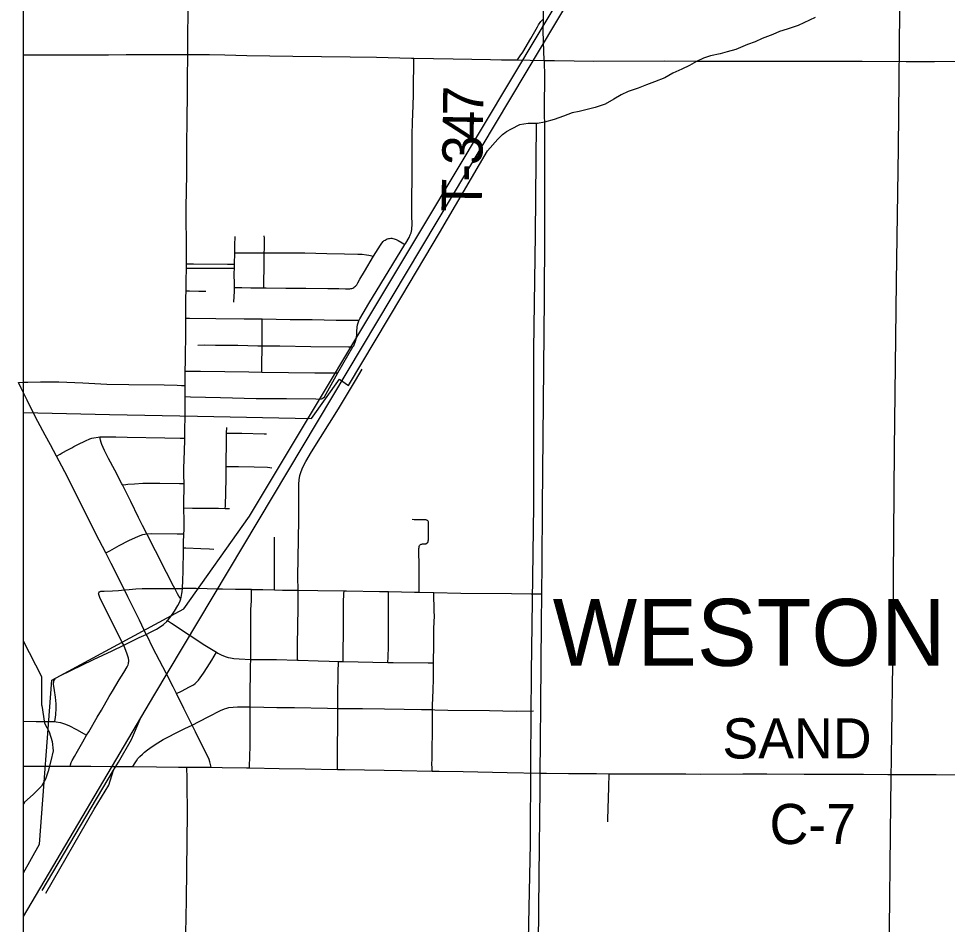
# Model space of a CAD drawing. Extents: x 0 to 680, y 0 to 834.
# Drawn here: x 44.4 to 94.9, y 268.9 to 318.1 of the extents above; entities that cross this region are included whole.
import ezdxf

# ---------------------------------------------------------------- set-up
doc = ezdxf.new("R2010")
doc.units = 0
for name, color, linetype in [('GM_X_City_Street', 7, 'Continuous'), ('GM_X_Corporation_Text', 7, 'Continuous'), ('GM_X_County_Road', 7, 'Continuous'), ('GM_X_County_Road_Text', 7, 'Continuous'), ('GM_X_Interstate_Route', 7, 'Continuous'), ('GM_X_Minor_River', 7, 'Continuous'), ('GM_X_Rail_Line', 7, 'Continuous'), ('GM_X_State_Route', 7, 'Continuous'), ('GM_X_Township_Road', 7, 'Continuous'), ('GM_X_Township_Road_Text', 7, 'Continuous')]:
    doc.layers.add(name, color=color, linetype=linetype)

msp = doc.modelspace()

# ---------------------------------------------------------------- linework, layer by layer
at = {"layer": 'GM_X_City_Street'}
for p, q in [((56.152, 304.76), (56.17, 305.388)), ((61.777, 298.858), (62.588, 300.27))]:
    msp.add_line(p, q, dxfattribs=at)
for points in [[(56.17, 305.388), (56.172, 305.444), (56.17, 305.803), (56.188, 306.278)], [(57.775, 305.391), (57.777, 305.6), (57.777, 306.184), (57.774, 306.301)], [(62.793, 300.988), (62.797, 301.108), (62.81, 301.349), (62.831, 301.466), (62.866, 301.581), (62.911, 301.692), (62.927, 301.724), (62.964, 301.8), (63.143, 302.113), (63.458, 302.626), (65.415, 305.836), (65.463, 305.915), (65.647, 306.223), (65.705, 306.361)], [(63.71, 305.198), (63.829, 305.398), (64.08, 305.807), (64.15, 305.908), (64.233, 306.001), (64.282, 306.046), (64.332, 306.08), (64.398, 306.117), (64.445, 306.138), (64.511, 306.158), (64.569, 306.169), (64.641, 306.175), (64.696, 306.173), (64.754, 306.164), (64.82, 306.15), (64.938, 306.108), (65.049, 306.054), (65.256, 305.93), (65.415, 305.836)], [(56.17, 305.388), (56.63, 305.388), (57.775, 305.391)], [(57.741, 303.485), (57.749, 303.843), (57.764, 304.545), (57.775, 305.391)], [(57.741, 303.485), (57.874, 303.483), (58.951, 303.466), (60.029, 303.464), (61.227, 303.442), (61.826, 303.439), (62.185, 303.421), (62.302, 303.421), (62.417, 303.43), (62.475, 303.442), (62.529, 303.455), (62.576, 303.471), (62.632, 303.499), (62.677, 303.529), (62.72, 303.564), (62.755, 303.6), (62.792, 303.649), (62.851, 303.748), (62.963, 303.962), (63.216, 304.369), (63.71, 305.198)], [(57.775, 305.391), (57.946, 305.392), (59.262, 305.384), (59.98, 305.377), (61.176, 305.347), (62.133, 305.334), (62.852, 305.319), (63.092, 305.305), (63.332, 305.273), (63.451, 305.249), (63.71, 305.198)], [(53.554, 304.793), (53.932, 304.789), (55.771, 304.765), (56.152, 304.76)], [(56.149, 304.543), (56.151, 304.728), (56.152, 304.76)], [(53.55, 304.555), (53.838, 304.548), (55.359, 304.545), (55.672, 304.544), (56.149, 304.543)], [(56.148, 303.5), (56.149, 303.655), (56.146, 304.252), (56.149, 304.543)], [(53.536, 303.323), (53.715, 303.319), (54.221, 303.309), (54.598, 303.31)], [(56.126, 302.698), (56.147, 303.296), (56.148, 303.5)], [(56.148, 303.5), (56.558, 303.494), (57.035, 303.489), (57.741, 303.485)], [(53.522, 301.839), (53.715, 301.836), (55.142, 301.821), (56.688, 301.801), (57.52, 301.792), (57.663, 301.789)], [(57.65, 300.335), (57.652, 300.754), (57.662, 301.458), (57.662, 301.575), (57.663, 301.789)], [(57.663, 301.789), (59.185, 301.769), (60.374, 301.754), (61.683, 301.73), (62.753, 301.725), (62.927, 301.724)], [(62.588, 300.27), (62.628, 300.339), (62.728, 300.592), (62.776, 300.771), (62.793, 300.988)], [(54.172, 300.375), (54.532, 300.38), (55.133, 300.371), (56.335, 300.359), (57.416, 300.339), (57.65, 300.335)], [(57.641, 298.904), (57.643, 299.228), (57.65, 300.335)], [(57.65, 300.335), (58.618, 300.323), (60.3, 300.299), (62.343, 300.273), (62.588, 300.27)], [(53.473, 297.571), (53.769, 297.564), (55.387, 297.523), (57.331, 297.474), (58.975, 297.463), (60.572, 297.443), (60.768, 297.433), (60.872, 297.447), (60.923, 297.466), (60.979, 297.505), (61.035, 297.567), (61.777, 298.858)], [(53.478, 298.954), (53.709, 298.957), (53.828, 298.959), (54.307, 298.953), (55.622, 298.937), (56.938, 298.913), (57.641, 298.904)], [(57.641, 298.904), (59.091, 298.884), (60.527, 298.864), (61.484, 298.86), (61.777, 298.858)], [(59.578, 283.256), (59.577, 283.474), (59.576, 284.073), (59.605, 286.107), (59.608, 286.826), (59.605, 287.051), (59.599, 287.783), (59.625, 289.818), (59.644, 290.893), (59.647, 292.447), (59.649, 292.806), (59.672, 293.045), (59.712, 293.281), (59.74, 293.397), (59.776, 293.511), (59.868, 293.732), (60.035, 294.05), (60.343, 294.564), (61.797, 296.904), (62.722, 298.444), (63.088, 299.063)], [(44.429, 298.336), (44.696, 298.351), (44.934, 298.365), (45.618, 298.383), (46.623, 298.371), (47.925, 298.32), (49.228, 298.251), (50.42, 298.222), (52.33, 298.206), (53.046, 298.194), (53.284, 298.183), (53.472, 298.175)], [(55.656, 291.495), (55.66, 291.637), (55.699, 293.115), (55.707, 293.772), (55.725, 295.287), (55.73, 295.589), (55.736, 295.89)], [(46.493, 294.343), (46.685, 294.452), (46.789, 294.511), (47.106, 294.684), (47.213, 294.733), (47.32, 294.789), (47.425, 294.853), (47.639, 294.965), (48.071, 295.177), (48.292, 295.271), (48.406, 295.309), (48.521, 295.338), (48.758, 295.373), (48.835, 295.379), (48.998, 295.391), (49.72, 295.39), (50.322, 295.371), (52.367, 295.338), (53.209, 295.322), (53.456, 295.317)], [(53.243, 286.578), (53.14, 286.731), (53.06, 286.85), (52.91, 287.151), (52.849, 287.276), (52.465, 288.018), (51.867, 289.193), (51.43, 290.044), (51.403, 290.118), (51.155, 290.574), (50.941, 291.003), (50.522, 291.868), (50.077, 292.771), (50.045, 292.837), (49.652, 293.579), (49.316, 294.216), (49.099, 294.644), (48.95, 294.971), (48.906, 295.083), (48.878, 295.198), (48.835, 295.379)], [(55.73, 295.589), (55.953, 295.588), (56.559, 295.583), (57.772, 295.55), (57.893, 295.55)], [(55.707, 293.772), (55.89, 293.772), (56.374, 293.771), (57.222, 293.758), (57.948, 293.731), (58.068, 293.721), (58.187, 293.697)], [(50.077, 292.771), (50.249, 292.795), (50.366, 292.811), (50.717, 292.84), (51.182, 292.862), (51.642, 292.873), (52.109, 292.871), (53.169, 292.854), (53.416, 292.85)], [(53.405, 291.524), (53.883, 291.518), (54, 291.514), (54.234, 291.507), (54.586, 291.502), (55.289, 291.506), (55.656, 291.495), (55.878, 291.489)], [(66.192, 286.949), (66.19, 287.19), (66.179, 288.255), (66.176, 289.319), (66.18, 289.373), (66.191, 289.436), (66.211, 289.478), (66.229, 289.507), (66.255, 289.533), (66.287, 289.55), (66.323, 289.562), (66.364, 289.57), (66.485, 289.568), (66.517, 289.571), (66.542, 289.577), (66.572, 289.586), (66.599, 289.599), (66.624, 289.619), (66.652, 289.651), (66.671, 289.693), (66.68, 289.737), (66.688, 289.792), (66.698, 290.503), (66.701, 290.622), (66.699, 290.692), (66.692, 290.74), (66.685, 290.769), (66.671, 290.799), (66.657, 290.821), (66.635, 290.842), (66.61, 290.858), (66.575, 290.867), (66.547, 290.872), (66.512, 290.875), (66.276, 290.88), (65.921, 290.881), (65.803, 290.888)], [(49.166, 289.076), (49.379, 289.196), (49.892, 289.484), (50.416, 289.751), (50.951, 289.995), (51.172, 290.078), (51.286, 290.104), (51.403, 290.118), (51.638, 290.127), (53.05, 290.113), (53.168, 290.114), (53.41, 290.115)], [(58.323, 287.072), (58.323, 287.175), (58.336, 289.927)], [(53.395, 289.355), (53.513, 289.351), (54.332, 289.322), (54.799, 289.302), (55.032, 289.285)], [(48.825, 286.968), (48.857, 286.983), (48.889, 286.994), (48.914, 287.001), (48.948, 287.004), (48.992, 287.006), (49.071, 287.006), (49.533, 287.012), (49.86, 287.036), (50.18, 287.068), (50.444, 287.1), (50.797, 287.126), (51.149, 287.141), (51.5, 287.15), (51.961, 287.154), (52.307, 287.153), (52.91, 287.151), (53.013, 287.152), (53.338, 287.153)], [(52.524, 285.406), (52.556, 285.439), (52.702, 285.623), (52.895, 285.919), (53.08, 286.22), (53.188, 286.428), (53.231, 286.537), (53.243, 286.578), (53.264, 286.649), (53.304, 286.881), (53.315, 286.961), (53.338, 287.153)], [(57.087, 287.086), (57.693, 287.084), (58.323, 287.072), (58.768, 287.064), (59.605, 287.051), (60.68, 287.035), (62.103, 287.02), (62.233, 287.019), (64.024, 286.985), (64.516, 286.977), (65.934, 286.955), (66.192, 286.949), (66.982, 286.932), (68.443, 286.9), (71.192, 286.866), (72.268, 286.857), (72.627, 286.857), (72.847, 286.858)], [(50.137, 284.063), (50.045, 284.247), (49.369, 285.607), (49.103, 286.132), (48.848, 286.661), (48.789, 286.819), (48.782, 286.846), (48.776, 286.871), (48.784, 286.916), (48.825, 286.968)], [(62.054, 283.177), (62.056, 283.386), (62.06, 283.725), (62.073, 284.757), (62.074, 285.587), (62.075, 286.162), (62.077, 286.506), (62.093, 286.741), (62.097, 286.86), (62.103, 287.02)], [(64.49, 283.126), (64.498, 283.416), (64.514, 283.986), (64.52, 284.832), (64.522, 285.196), (64.525, 285.661), (64.516, 286.613), (64.516, 286.733), (64.516, 286.977)], [(66.893, 277.23), (66.886, 277.447), (66.882, 277.566), (66.886, 277.926), (66.892, 278.165), (66.892, 278.404), (66.892, 278.524), (66.911, 279.243), (66.902, 279.842), (66.906, 280.564), (66.91, 280.676), (66.915, 280.795), (66.939, 281.63), (66.945, 281.749), (66.967, 282.107), (66.964, 282.586), (66.969, 283.064), (66.969, 283.108), (66.97, 283.183), (66.968, 283.542), (66.975, 283.662), (66.985, 284.14), (66.99, 284.497), (66.989, 284.968), (67, 285.32), (67.009, 285.669), (67, 285.897), (66.992, 286.12), (66.985, 286.704), (66.982, 286.932)], [(51.367, 284.654), (51.602, 284.765), (51.913, 284.931), (52.112, 285.057), (52.3, 285.197), (52.475, 285.354), (52.524, 285.406)], [(52.524, 285.406), (52.742, 285.262), (53.741, 284.601), (54.541, 284.074), (55.172, 283.683), (55.254, 283.632), (55.471, 283.523), (55.696, 283.433), (55.814, 283.4), (55.934, 283.378), (56.111, 283.334), (56.415, 283.321), (57.036, 283.295), (57.367, 283.281), (57.487, 283.282), (58.441, 283.281), (59.578, 283.256), (59.635, 283.254), (60.708, 283.21), (61.302, 283.191), (61.773, 283.183), (61.807, 283.182), (62.054, 283.177), (64.49, 283.126), (64.765, 283.12), (66.682, 283.109), (66.969, 283.108)], [(46.374, 282.192), (46.408, 282.236), (46.44, 282.266), (46.468, 282.289), (46.674, 282.408), (48.506, 283.287), (49.517, 283.765), (50.137, 284.063), (50.622, 284.296), (50.986, 284.475), (51.367, 284.654)], [(47.229, 277.494), (47.25, 277.57), (47.284, 277.689), (47.34, 277.809), (47.463, 278.014), (47.634, 278.316), (47.924, 278.816), (48.126, 279.177), (48.241, 279.367), (48.692, 280.147), (48.935, 280.544), (49.343, 281.27), (49.523, 281.577), (49.706, 281.882), (49.9, 282.18), (50.141, 282.589), (50.321, 282.897), (50.375, 283.004), (50.396, 283.063), (50.406, 283.118), (50.412, 283.182), (50.41, 283.236), (50.396, 283.354), (50.327, 283.581), (50.137, 284.063)], [(53.003, 281.434), (53.277, 281.575), (53.711, 281.798), (53.921, 281.921), (54.021, 281.993), (54.111, 282.074), (54.193, 282.162), (54.478, 282.548), (54.679, 282.851), (54.929, 283.261), (55.048, 283.468), (55.172, 283.683)], [(61.752, 277.319), (61.751, 277.586), (61.75, 278.177), (61.75, 278.767), (61.765, 279.475), (61.767, 280.532), (61.768, 280.632), (61.777, 281.7), (61.78, 282.167), (61.79, 282.759), (61.799, 282.995), (61.807, 283.182)], [(46.407, 279.914), (46.434, 280.161), (46.448, 280.279), (46.464, 280.639), (46.463, 280.88), (46.433, 281.241), (46.382, 281.6), (46.343, 281.838), (46.335, 281.957), (46.334, 282.019), (46.339, 282.076), (46.353, 282.136), (46.374, 282.192)], [(53.848, 279.724), (54.238, 279.914), (54.762, 280.196), (55.401, 280.515), (55.62, 280.61), (55.733, 280.648), (55.849, 280.675), (56.086, 280.706), (56.322, 280.714), (57.006, 280.708), (57.746, 280.699), (58.46, 280.688), (59.416, 280.684), (61.201, 280.641), (61.768, 280.632), (62.507, 280.618), (63.105, 280.622), (64.298, 280.61), (65.367, 280.598), (66.318, 280.573), (66.906, 280.564), (67.029, 280.562), (67.742, 280.539), (70.001, 280.51), (71.457, 280.487), (72.39, 280.505)], [(44.693, 279.935), (45.393, 279.926), (46.231, 279.926), (46.35, 279.921), (46.407, 279.914), (46.469, 279.907), (46.703, 279.858), (46.931, 279.787), (47.152, 279.696), (47.578, 279.477), (47.998, 279.249), (48.126, 279.177)], [(50.638, 277.472), (50.753, 277.666), (50.826, 277.789), (50.906, 277.901), (51.023, 278.015), (51.152, 278.143), (51.262, 278.248), (51.439, 278.383), (51.693, 278.558), (51.992, 278.752), (52.285, 278.936), (52.646, 279.132), (52.875, 279.252), (53.457, 279.535), (53.848, 279.724)], [(76.43, 274.474), (76.43, 274.591), (76.477, 276.361), (76.504, 277.085)]]:
    msp.add_lwpolyline(points, dxfattribs=at)
at = {"layer": 'GM_X_County_Road'}
for p, q in [((75.808, 277.088), (76.504, 277.085)), ((81.467, 277.067), (83.757, 277.077))]:
    msp.add_line(p, q, dxfattribs=at)
for points in [[(44.693, 277.496), (45.265, 277.502), (46.454, 277.491), (47.168, 277.494), (47.229, 277.494)], [(47.229, 277.494), (48.358, 277.49), (49.549, 277.483), (50.501, 277.474), (50.638, 277.472)], [(50.638, 277.472), (51.927, 277.459), (53.12, 277.441), (53.568, 277.442)], [(53.568, 277.442), (53.835, 277.442), (54.881, 277.434)], [(54.881, 277.434), (55.494, 277.429), (56.799, 277.405), (56.964, 277.402)], [(56.964, 277.402), (58.575, 277.371), (60.002, 277.353), (61.752, 277.319)], [(61.752, 277.319), (62.146, 277.311), (64.291, 277.274), (65.244, 277.258), (66.893, 277.23)], [(66.893, 277.23), (67.269, 277.223), (68.578, 277.205), (70.96, 277.157), (72.759, 277.117)], [(72.759, 277.117), (73.098, 277.114), (74.303, 277.103), (75.267, 277.09), (75.808, 277.088)], [(76.504, 277.085), (77.166, 277.083), (79.438, 277.074)], [(79.438, 277.074), (79.814, 277.072), (80.663, 277.071), (81.467, 277.067)], [(83.757, 277.077), (85.068, 277.073), (87.098, 277.064), (88.769, 277.055), (90.321, 277.055), (91.634, 277.042), (94.261, 277.037), (98.44, 276.987), (99.634, 276.98), (100.115, 276.992), (100.239, 277.005)]]:
    msp.add_lwpolyline(points, dxfattribs=at)
at = {"layer": 'GM_X_Interstate_Route'}
msp.add_lwpolyline([(44.693, 394.069), (374.693, 394.069), (374.693, 64.069), (44.693, 64.069)], close=True, dxfattribs=at)
at = {"layer": 'GM_X_Minor_River'}
for points in [[(92.297, 320.37), (92.2, 311.072), (92.094, 303.817), (91.987, 294.711), (91.894, 283.026), (91.784, 275.495), (91.7, 266.958), (91.604, 257.679), (91.536, 248.37), (91.449, 240.548), (91.442, 230.554), (91.365, 219.848), (91.291, 211.968), (91.2, 203.054), (91.208, 197.474), (91.042, 190.192), (90.977, 182.865), (90.897, 176.367), (90.732, 166.476)], [(87.687, 318.171), (86.777, 317.734), (86.162, 317.54), (85.752, 317.401), (85.385, 317.247), (84.814, 317.038), (84.432, 316.855), (84.022, 316.702), (83.377, 316.436), (82.908, 316.298), (82.528, 316.202), (82.002, 316.094), (81.621, 315.955), (81.239, 315.772), (80.872, 315.559), (80.446, 315.362), (79.962, 315.137), (79.521, 314.897), (78.963, 314.673), (78.538, 314.505), (78.084, 314.324), (77.528, 314.158), (77.16, 313.975), (76.749, 313.734), (76.278, 313.465), (75.736, 313.285), (75.239, 313.162), (74.873, 313.066), (74.493, 312.985), (74.024, 312.803), (73.512, 312.637), (73, 312.485), (72.62, 312.419), (72.11, 312.413), (71.643, 312.333), (71.173, 312.108), (70.908, 311.967)], [(72.531, 312.418), (72.49, 306.389), (72.401, 300.139), (72.391, 291.63), (72.269, 282.599), (72.232, 277.748), (72.217, 273.29), (72.043, 265.454), (72.036, 257.165), (71.953, 250.45), (71.867, 242.716), (71.808, 234.821), (71.709, 227.13), (71.59, 218.304)], [(44.693, 296.715), (49.375, 296.603), (54.15, 296.504), (60.338, 296.382), (61.859, 298.512), (62.348, 298.169), (65.24, 303.029), (67.292, 306.462), (69.901, 310.92), (70.465, 311.567), (70.702, 311.81), (70.908, 311.967)], [(45.689, 280.788), (45.686, 282.346), (44.693, 284.276)], [(45.689, 280.788), (45.833, 279.823), (46.087, 279.353), (46.254, 278.84), (46.303, 278.329), (46.178, 277.778), (46.037, 277.226), (45.885, 276.792), (45.674, 276.402), (45.23, 275.959), (44.757, 275.545), (44.693, 275.444)]]:
    msp.add_lwpolyline(points, dxfattribs=at)
at = {"layer": 'GM_X_Rail_Line'}
msp.add_line((45.702, 270.738), (49.592, 277.277), dxfattribs=at)
for points in [[(44.693, 269.332), (51.769, 281.322), (75.212, 320.593), (96.666, 356.59), (117.676, 391.917), (118.957, 394.069)], [(44.693, 271.705), (45.564, 273.256), (46.237, 282.165), (53.398, 286.034), (56.977, 291.069), (66.552, 307.049), (99.131, 361.526), (117.724, 392.753), (118.508, 394.069)], [(49.592, 277.277), (49.853, 277.714), (50.563, 278.945), (51.08, 280.169)], [(45.907, 270.596), (48.543, 275.158), (49.332, 276.452), (49.592, 277.277)]]:
    msp.add_lwpolyline(points, dxfattribs=at)
at = {"layer": 'GM_X_State_Route'}
for points in [[(73.001, 306.309), (73.016, 308.986), (73.007, 311.972), (72.993, 313.286), (73.004, 314.957), (72.983, 315.792), (72.981, 315.841), (72.935, 316.866), (72.927, 317.464), (72.935, 318.1), (72.957, 319.734)], [(72.787, 280.857), (72.831, 285.271), (72.847, 286.858), (72.864, 288.492), (72.888, 291.594), (72.992, 302.927), (73.001, 306.309)], [(72.759, 277.117), (72.767, 278.829), (72.787, 280.857)], [(72.655, 267.088), (72.656, 267.124), (72.668, 267.858), (72.699, 271.538), (72.748, 276.287), (72.759, 277.117)]]:
    msp.add_lwpolyline(points, dxfattribs=at)
at = {"layer": 'GM_X_Township_Road'}
for points in [[(53.624, 316.161), (53.624, 316.586), (53.631, 319.015), (53.662, 321.394), (53.661, 323.667), (53.685, 324.959), (53.689, 326.063), (53.692, 327.036), (53.699, 328.892), (53.708, 330.708), (53.714, 331.852), (53.722, 332.973), (53.704, 334.436), (53.712, 335.548), (53.72, 337.323), (53.734, 340.078), (53.733, 342.131), (53.741, 344.388), (53.756, 345.688), (53.772, 347.732), (53.785, 349.997), (53.794, 351.395), (53.818, 353.112), (53.837, 354.447)], [(71.53, 315.865), (71.6, 315.976), (71.673, 316.093), (71.812, 316.294), (72.245, 317.033), (72.603, 317.671), (72.667, 317.773), (72.789, 317.947), (72.839, 318.004), (72.935, 318.1)], [(44.693, 316.137), (45.018, 316.141), (46.57, 316.134), (48.002, 316.141), (49.314, 316.141), (50.267, 316.152), (52.175, 316.168), (53.128, 316.163), (53.624, 316.161)], [(53.538, 307.378), (53.538, 307.951), (53.546, 308.663), (53.562, 309.734), (53.566, 310.209), (53.572, 310.684), (53.576, 311.043), (53.585, 312.817), (53.6, 313.847), (53.6, 314.828), (53.624, 316.161)], [(53.624, 316.161), (54.793, 316.156), (55.627, 316.134), (56.82, 316.112), (59.327, 316.071), (62.43, 316.029), (63.862, 316.006), (65.772, 315.967), (65.9, 315.966)], [(65.805, 310.941), (65.808, 311.787), (65.825, 312.485), (65.856, 313.396), (65.873, 313.985), (65.882, 314.895), (65.899, 315.234), (65.891, 315.699), (65.9, 315.966)], [(65.9, 315.966), (66.965, 315.951), (68.039, 315.926), (70.068, 315.887), (70.664, 315.875), (71.53, 315.865)], [(71.53, 315.865), (72.215, 315.857), (72.981, 315.841)], [(72.981, 315.841), (73.527, 315.83), (74.601, 315.807), (75.675, 315.803), (79.495, 315.81), (81.285, 315.799), (82.598, 315.79), (84.031, 315.799), (85.582, 315.803), (90.238, 315.789), (92.625, 315.781), (94.177, 315.783), (95.49, 315.792), (102.175, 315.786), (103.488, 315.775), (105.398, 315.767), (107.666, 315.764), (110.412, 315.76), (111.247, 315.749), (111.825, 315.686)], [(65.705, 306.361), (65.745, 306.477), (65.767, 306.557), (65.782, 306.656), (65.792, 306.744), (65.797, 306.864), (65.79, 307.466), (65.798, 310.355), (65.805, 310.941)], [(53.549, 306.431), (53.539, 306.766), (53.538, 307.378)], [(53.55, 304.555), (53.554, 304.793), (53.556, 304.925), (53.552, 305.519), (53.551, 305.865), (53.547, 306.224), (53.549, 306.431)], [(53.536, 303.323), (53.53, 303.635), (53.538, 303.867), (53.55, 304.555)], [(53.478, 298.954), (53.488, 299.524), (53.517, 301.175), (53.52, 301.524), (53.522, 301.839), (53.516, 302.187), (53.516, 302.947), (53.536, 303.323)], [(53.472, 298.175), (53.471, 298.573), (53.478, 298.954)], [(46.493, 294.343), (46.171, 294.96), (45.882, 295.48), (45.481, 296.212), (45.207, 296.742), (44.888, 297.382), (44.574, 298.025), (44.429, 298.336)], [(53.473, 297.571), (53.472, 297.861), (53.472, 298.175)], [(53.456, 295.317), (53.456, 295.453), (53.459, 295.681), (53.461, 295.795), (53.461, 295.904), (53.463, 296.019), (53.468, 296.245), (53.474, 296.356), (53.472, 296.588), (53.47, 296.808), (53.469, 296.925), (53.473, 297.267), (53.473, 297.571)], [(53.416, 292.85), (53.41, 293.307), (53.411, 293.663), (53.448, 294.618), (53.457, 295.215), (53.456, 295.317)], [(49.166, 289.076), (48.81, 289.78), (48.323, 290.736), (47.844, 291.694), (46.939, 293.486), (46.777, 293.801), (46.493, 294.343)], [(53.405, 291.524), (53.405, 292.009), (53.421, 292.471), (53.416, 292.85)], [(53.41, 290.115), (53.417, 290.322), (53.419, 290.441), (53.421, 290.799), (53.405, 291.524)], [(53.395, 289.355), (53.393, 289.63), (53.41, 290.115)], [(50.18, 287.068), (49.454, 288.507), (49.166, 289.076)], [(53.338, 287.153), (53.358, 287.6), (53.363, 288.078), (53.395, 289.271), (53.395, 289.355)], [(51.367, 284.654), (51.001, 285.422), (50.366, 286.701), (50.18, 287.068)], [(57.087, 287.086), (56.218, 287.097), (55.503, 287.108), (55.265, 287.114), (54.672, 287.124), (54.078, 287.14), (53.721, 287.145), (53.338, 287.153)], [(57.036, 283.295), (57.041, 283.628), (57.042, 283.865), (57.045, 284.102), (57.044, 284.22), (57.043, 284.456), (57.046, 284.693), (57.044, 285.169), (57.038, 285.405), (57.045, 285.642), (57.052, 285.997), (57.073, 286.471), (57.087, 287.086)], [(53.003, 281.434), (52.817, 281.806), (52.437, 282.548), (51.721, 283.922), (51.41, 284.566), (51.367, 284.654)], [(57.006, 280.708), (57.006, 280.795), (57.009, 281.143), (57.006, 281.262), (57.011, 281.498), (57.032, 282.563), (57.03, 282.919), (57.036, 283.295)], [(53.848, 279.724), (53.403, 280.635), (53.003, 281.434)], [(56.964, 277.402), (56.972, 277.567), (56.982, 277.935), (56.988, 278.13), (56.998, 278.498), (56.999, 278.616), (57.003, 279.199), (57.001, 279.554), (57.004, 279.788), (57.002, 280.021), (57.004, 280.464), (57.006, 280.708)], [(54.881, 277.434), (54.851, 277.575), (54.819, 277.729), (54.781, 277.853), (54.031, 279.351), (53.848, 279.724)], [(53.495, 267.504), (53.541, 270.204), (53.561, 271.868), (53.599, 274.959), (53.594, 276.513), (53.58, 276.989), (53.573, 277.274), (53.568, 277.442)], [(53.568, 277.442), (53.835, 277.442), (54.881, 277.434)], [(54.881, 277.434), (55.494, 277.429), (56.799, 277.405), (56.964, 277.402)]]:
    msp.add_lwpolyline(points, dxfattribs=at)

# ---------------------------------------------------------------- texts
at = {"layer": 'GM_X_Corporation_Text'}
msp.add_text('WESTON', height=3.6364, rotation=0, dxfattribs=at).set_placement((73.437, 282.945))
at = {"layer": 'GM_X_County_Road_Text'}
for s, p in [('SAND', (82.653, 277.911)), ('C-7', (85.213, 273.261))]:
    msp.add_text(s, height=2.1818, rotation=0, dxfattribs=at).set_placement(p)
at = {"layer": 'GM_X_Township_Road_Text'}
for s, rotation, p in [('7', 89.2736, (69.655, 312.825)), ('4', 89.1578, (69.635, 311.476)), ('3', 89.1257, (69.614, 310.131)), ('-', 89.1336, (69.601, 309.235)), ('T', 89.1257, (69.576, 307.603))]:
    msp.add_text(s, height=2.182, rotation=rotation, dxfattribs=at).set_placement(p)

doc.saveas('drawing.dxf')
